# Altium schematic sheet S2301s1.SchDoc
size A3; SheetNumber: 1; SheetTotal: 1
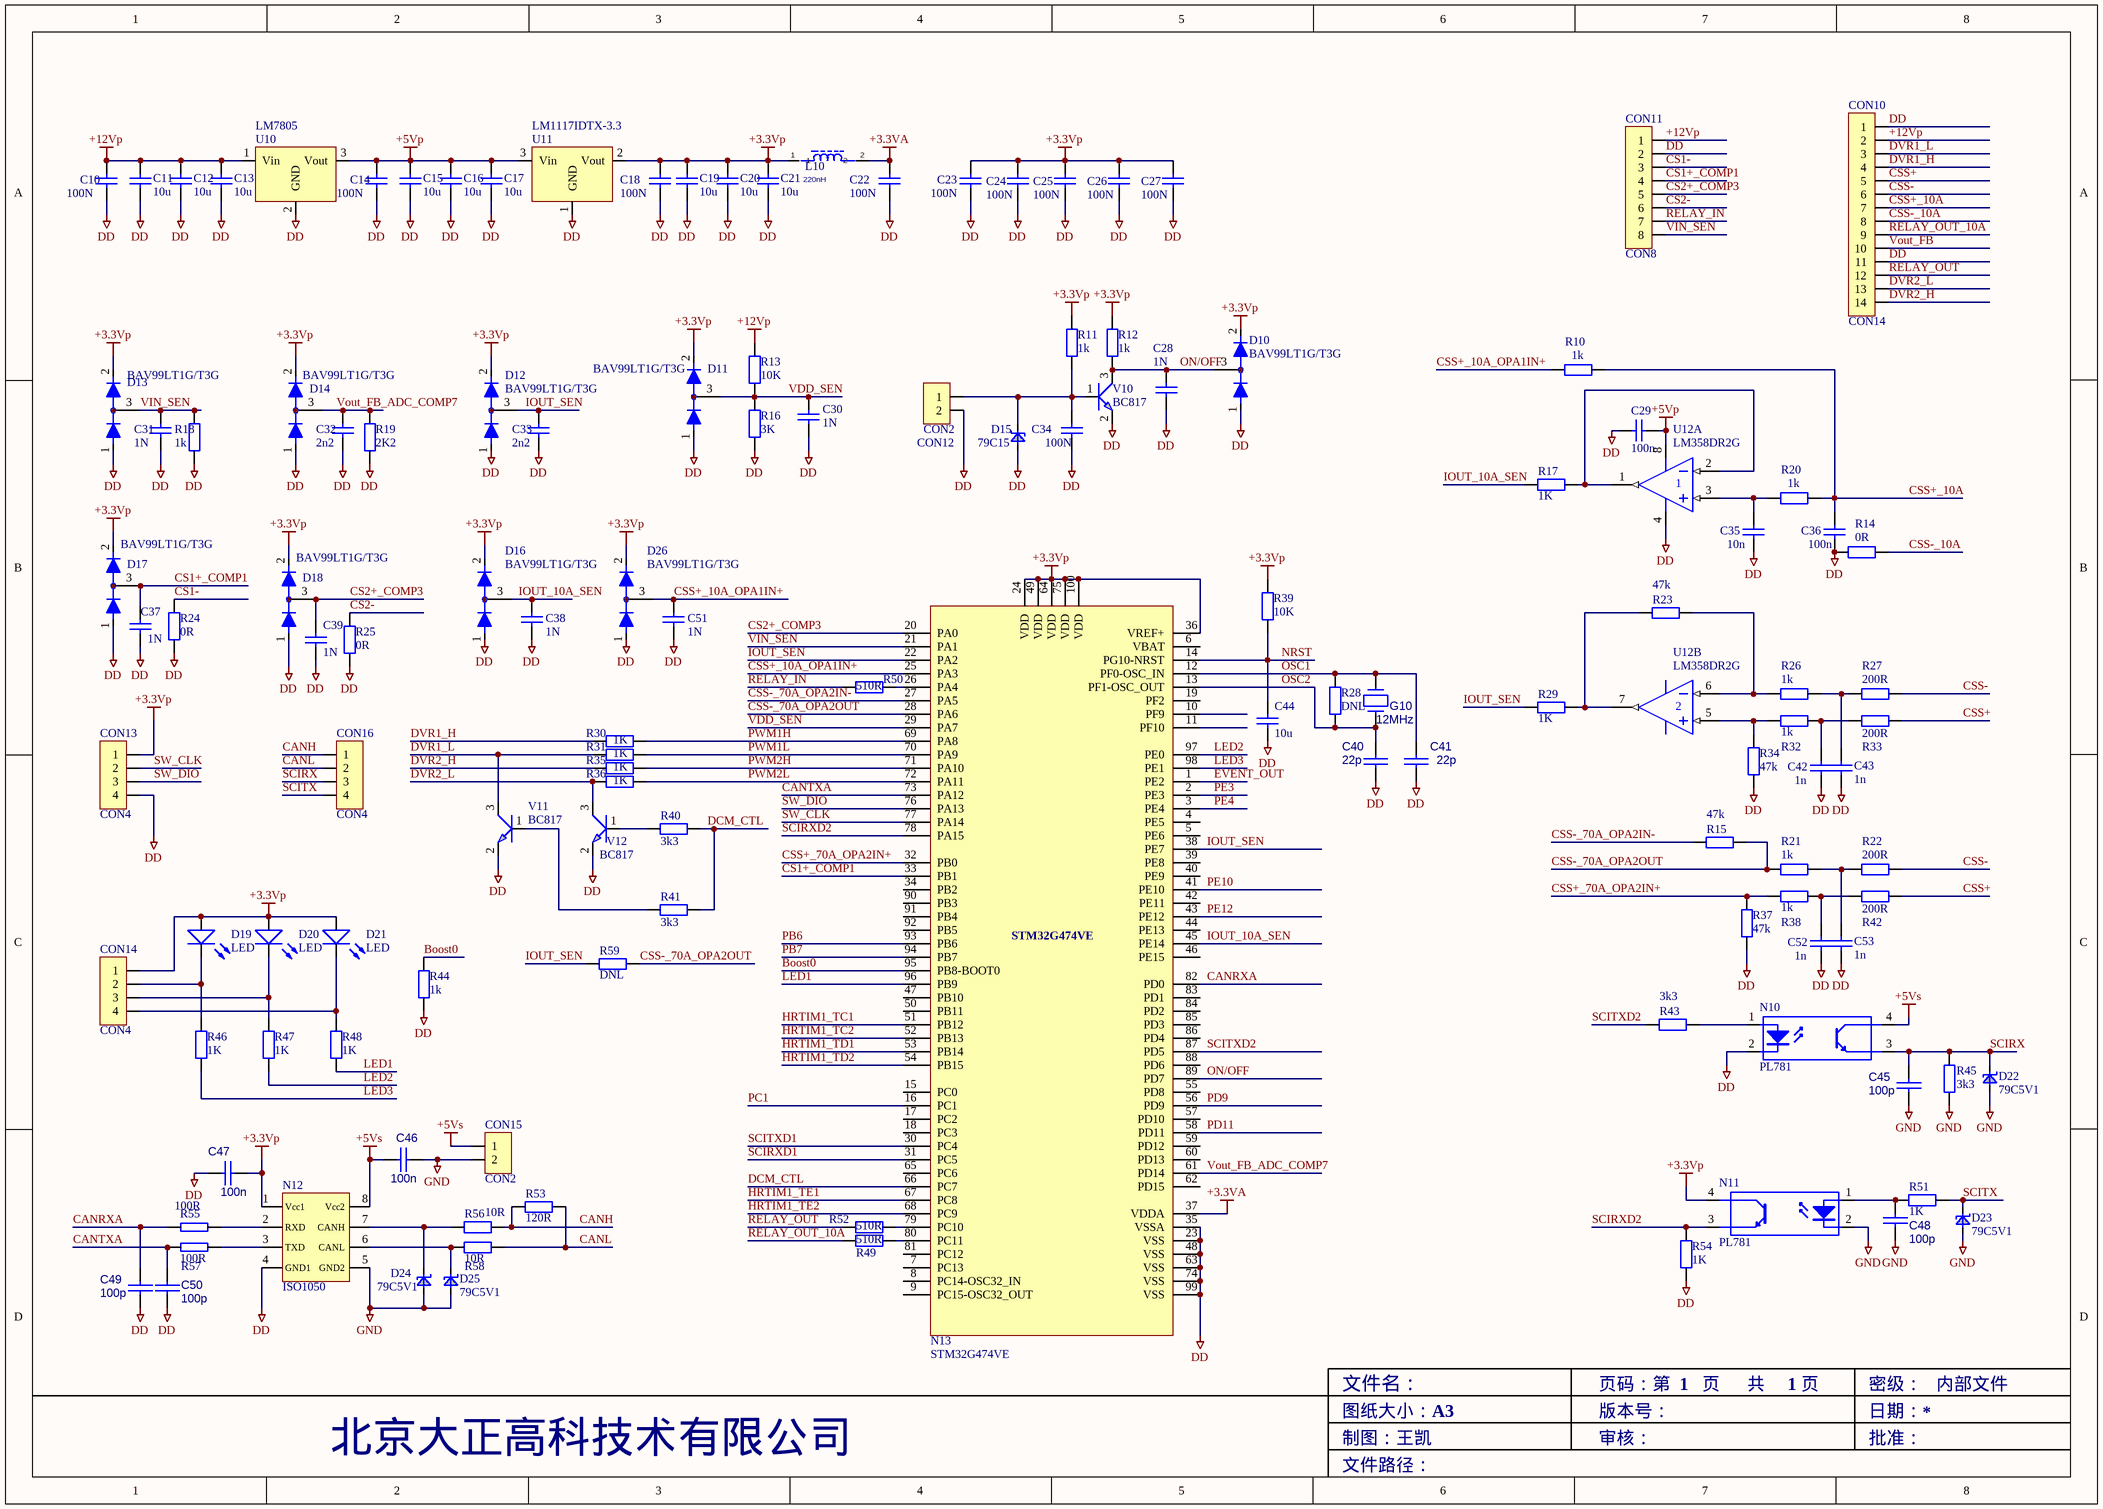
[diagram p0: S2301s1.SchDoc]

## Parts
C10  100N  [0805C]
C11  10u  [1210C]
C12  10u  [1210C]
C13  10u  [1210C]
C14  100N  [0805C]
C15  10u  [1210C]
C16  10u  [1210C]
C17  10u  [1210C]
C18  100N  [0805C]
C19  10u  [1210C]
C20  10u  [1210C]
C21  10u  [1210C]
C22  100N  [0805C]
C23  100N  [0805C]
C24  100N  [0805C]
C25  100N  [0805C]
C26  100N  [0805C]
C27  100N  [0805C]
C28  1N  [0805C]
C29  100n  [0805C]
C30  1N  [0805C]
C31  1N  [0805C]
C32  2n2  [0805C]
C33  2n2  [0805C]
C34  100N  [0805C]
C35  10n  [0805C]
C36  100n  [0805C]
C37  1N  [0805C]
C38  1N  [0805C]
C39  1N  [0805C]
C40  22p  [0805C]
C41  22p  [0805C]
C42  1n  [0805C]
C43  1n  [0805C]
C44  10u  [0805C]
C45  100p  [0805C]
C46  100n  [0805C]
C47  100n  [0805C]
C48  100p  [0805C]
C49  100p  [0805C]
C50  100p  [0805C]
C51  1N  [0805C]
C52  1n  [0805C]
C53  1n  [0805C]
CON10  CON14  [201S2X7]
CON11  CON8  [201S2X4]
CON12  CON2  [HEAD2X1]
CON13  CON4  [402+403-04]
CON14  CON4  [402+403-04]
CON15  CON2  [HEAD2X1]
CON16  CON4  [SIP4]
D10  BAV99LT1G/T3G  [SOT-23]
D11  BAV99LT1G/T3G  [SOT-23]
D12  BAV99LT1G/T3G  [SOT-23]
D13  BAV99LT1G/T3G  [SOT-23]
D14  BAV99LT1G/T3G  [SOT-23]
D15  79C15  [DO-214AC]
D16  BAV99LT1G/T3G  [SOT-23]
D17  BAV99LT1G/T3G  [SOT-23]
D18  BAV99LT1G/T3G  [SOT-23]
D19  LED  [0805_LED]
D20  LED  [0805_LED]
D21  LED  [0805_LED]
D22  79C5V1  [DO-214AC]
D23  79C5V1  [DO-214AC]
D24  79C5V1  [DO-214AC]
D25  79C5V1  [DO-214AC]
D26  BAV99LT1G/T3G  [SOT-23]
G10  12MHz  [XTAL-12MHz]
L10  220nH  [1206R]
N10  PL781  [SOP-4OPTO]
N11  PL781  [SOP-4OPTO]
N12  ISO1050  [6N136]
N13  STM32G474VE  [TQFP-100]
R10  1k  [0805R]
R11  1k  [0805R]
R12  1k  [0805R]
R13  10K  [0805R]
R14  0R  [0805R]
R15  47k  [0805R]
R16  3K  [0805R]
R17  1K  [0805R]
R18  1k  [0805R]
R19  2K2  [0805R]
R20  1k  [0805R]
R21  1k  [0805R]
R22  200R  [0805R]
R23  47k  [0805R]
R24  0R  [0805R]
R25  0R  [0805R]
R26  1k  [0805R]
R27  200R  [0805R]
R28  DNL  [0805R]
R29  1K  [0805R]
R30  1K  [0805R]
R31  1K  [0805R]
R32  1k  [0805R]
R33  200R  [0805R]
R34  47k  [0805R]
R35  1K  [0805R]
R36  1K  [0805R]
R37  47k  [0805R]
R38  1k  [0805R]
R39  10K  [0805R]
R40  3k3  [0805R]
R41  3k3  [0805R]
R42  200R  [0805R]
R43  3k3  [0805R]
R44  1k  [0805R]
R45  3k3  [0805R]
R46  1K  [0805R]
R47  1K  [0805R]
R48  1K  [0805R]
R49  510R  [0805R]
R50  510R  [0805R]
R51  1K  [0805R]
R52  510R  [0805R]
R53  120R  [0805R]
R54  1K  [0805R]
R55  100R  [0805R]
R56  10R  [0805R]
R57  100R  [0805R]
R58  10R  [0805R]
R59  DNL  [0805R]
U10  LM7805  [TO-220-1]
U11  LM1117IDTX-3.3  [TO-252]
U12  LM358DR2G  [SOIC-8]  (parts A,B of 2)
V10  BC817  [SOT-23]
V11  BC817  [SOT-23]
V12  BC817  [SOT-23]

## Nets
+3.3VA: C22.2 L10.2 N13.37(VDDA)
+3.3Vp: C18.2 C19.2 C20.2 C21.2 C23.2 C24.2 C25.2 C26.2 C27.2 C47.1 CON13.1 CON14.1 D10.2 D11.2 D12.2 D13.2 D14.2 D16.2 D17.2 D18.2 D19.A D20.A D21.A D26.2 L10.1 N11.4 N12.1(Vcc1) N13.24(VDD) N13.36(VREF+) N13.49(VDD) N13.64(VDD) N13.75(VDD) N13.100(VDD) R11.1 R12.2 R39.1 U11.2(Vout)
+5Vp: C14.2 C15.2 C16.2 C17.2 C29.1 U10.3(Vout) U11.3(Vin) U12.8(V+)
+5Vs: C46.2 CON15.1 N10.4 N12.8(Vcc2)
+12Vp: C10.2 C11.2 C12.2 C13.2 CON10.2 CON11.1 R13.2 U10.1(Vin)
DD: C10.1 C11.1 C12.1 C13.1 C14.1 C15.1 C16.1 C17.1 C18.1 C19.1 C20.1 C21.1 C22.1 C23.1 C24.1 C25.1 C26.1 C27.1 C28.1 C29.2 C30.1 C31.1 C32.1 C33.1 C34.1 C35.2 C36.2 C37.1 C38.1 C39.1 C40.2 C41.2 C42.2 C43.2 C44.1 C47.2 C49.1 C50.1 C51.1 C52.2 C53.2 CON10.1 CON10.11 CON11.2 CON12.2 CON13.4 D10.1 D11.1 D12.1 D13.1 D14.1 D15.A D16.1 D17.1 D18.1 D26.1 N10.2 N12.4(GND1) N13.23(VSS) N13.35(VSSA) N13.48(VSS) N13.63(VSS) N13.74(VSS) N13.99(VSS) R14.1 R16.1 R18.1 R19.1 R24.1 R25.1 R34.1 R37.1 R44.1 R54.2 U10.2(GND) U11.1(GND) U12.4(V-) V10.2(C) V11.2(C) V12.2(C)
GND: C45.1 C46.1 C48.1 CON15.2 D22.A D23.A D24.A D25.A N11.2 N12.5(GND2) R45.1
Boost0: N13.95(PB8-BOOT0) R44.2
CANH: CON16.1 R53.1 R56.1
CANL: CON16.2 R53.2 R58.1
CANRXA: C49.2 N13.82(PD0) R55.1
CANTXA: C50.2 N13.73(PA12) R57.1
CS1+_COMP1: C37.2 CON11.4 D17.3 N13.33(PB1)
CS1-: CON11.3 R24.2
CS2+_COMP3: C39.2 CON11.5 D18.3 N13.20(PA0)
CS2-: CON11.6 R25.2
CSS+: CON10.5 R33.2 R42.2
CSS+_10A: C36.1 CON10.7 R10.2 R20.2
CSS+_10A_OPA1IN+: C51.2 D26.3 N13.25(PA3) R10.1
CSS+_70A_OPA2IN+: N13.32(PB0) R37.2 R38.1
CSS-: CON10.6 R22.2 R27.2
CSS-_10A: CON10.8 R14.2
CSS-_70A_OPA2IN-: N13.27(PA5) R15.1
CSS-_70A_OPA2OUT: N13.28(PA6) R15.2 R21.1 R59.1
DCM_CTL: N13.66(PC7) R40.2 R41.2
DVR1_H: CON10.4 R30.1
DVR1_L: CON10.3 R31.1 V11.3(E)
DVR2_H: CON10.14 R35.1
DVR2_L: CON10.13 R36.1 V12.3(E)
EVENT_OUT: N13.1(PE2)
HRTIM1_TC1: N13.51(PB12)
HRTIM1_TC2: N13.52(PB13)
HRTIM1_TD1: N13.53(PB14)
HRTIM1_TD2: N13.54(PB15)
HRTIM1_TE1: N13.67(PC8)
HRTIM1_TE2: N13.68(PC9)
IOUT_10A_SEN: C38.2 D16.3 N13.45(PE14) R17.1
IOUT_SEN: C33.2 D12.3 N13.22(PA2) N13.38(PE7) R29.1 R59.2
LED1: N13.96(PB9) R48.1
LED2: N13.97(PE0) R47.2
LED3: N13.98(PE1) R46.2
NRST: C44.2 N13.14(PG10-NRST) R39.2
ON/OFF: C28.2 D10.3 N13.89(PD7) R12.1 V10.3(E)
OSC1: C41.1 G10.2 N13.12(PF0-OSC_IN) R28.2
OSC2: C40.1 G10.1 N13.13(PF1-OSC_OUT) R28.1
PB6: N13.93(PB6)
PB7: N13.94(PB7)
PC1: N13.16(PC1)
PD9: N13.56(PD9)
PD11: N13.58(PD11)
PE3: N13.2(PE3)
PE4: N13.3(PE4)
PE10: N13.41(PE10)
PE12: N13.43(PE12)
PWM1H: N13.69(PA8) R30.2
PWM1L: N13.70(PA9) R31.2
PWM2H: N13.71(PA10) R35.2
PWM2L: N13.72(PA11) R36.2
RELAY_IN: CON11.7 R50.1
RELAY_OUT: CON10.12 R52.1
RELAY_OUT_10A: CON10.9 R49.2
SCIRX: C45.2 CON16.3 D22.K N10.3 R45.2
SCIRXD1: N13.31(PC5)
SCIRXD2: N11.3 N13.78(PA15) R54.1
SCITX: CON16.4 D23.K R51.1
SCITXD1: N13.30(PC4)
SCITXD2: N13.87(PD5) R43.2
SW_CLK: CON13.2 N13.77(PA14)
SW_DIO: CON13.3 N13.76(PA13)
VDD_SEN: C30.2 D11.3 N13.29(PA7) R13.1 R16.2
VIN_SEN: C31.2 CON11.8 D13.3 N13.21(PA1) R18.2
Vout_FB: CON10.10
Vout_FB_ADC_COMP7: C32.2 D14.3 N13.61(PD14) R19.2
NetC34_2: C34.2 CON12.1 D15.K R11.2 V10.1(B)
NetC35_1: C35.1 R20.1 U12.3(IN+)
NetC42_1: C42.1 R32.2 R33.1
NetC43_1: C43.1 R26.2 R27.1
NetC48_2: C48.2 N11.1 R51.2
NetC52_1: C52.1 R38.2 R42.1
NetC53_1: C53.1 R21.2 R22.1
NetCON14_2: CON14.2 D19.K R46.1
NetCON14_3: CON14.3 D20.K R47.1
NetCON14_4: CON14.4 D21.K R48.2
NetD24_K: D24.K N12.7(CANH) R56.2
NetD25_K: D25.K N12.6(CANL) R58.2
NetN10_1: N10.1 R43.1
NetN12_2: N12.2(RXD) R55.2
NetN12_3: N12.3(TXD) R57.2
NetN13_26: N13.26(PA4) R50.2
NetN13_79: N13.79(PC10) R52.2
NetN13_80: N13.80(PC11) R49.1
NetR17_2: R17.2 U12.1(OUT) U12.2(IN-)
NetR23_1: R23.1 R29.2 U12.7(OUT)
NetR23_2: R23.2 R26.1 U12.6(IN-)
NetR32_1: R32.1 R34.2 U12.5(IN+)
NetR40_1: R40.1 V12.1(B)
NetR41_1: R41.1 V11.1(B)

Not connected (* = marked no-connect by the designer): N13 4(PE5) 5(PE6) 6(VBAT) 7(PC13) 8(PC14-OSC32_IN) 9(PC15-OSC32_OUT) 10(PF9) 11(PF10) 15(PC0) 17(PC2) 18(PC3) 19(PF2) 34(PB2) 39(PE8) 40(PE9) 42(PE11) 44(PE13) 46(PE15) 47(PB10) 50(PB11) 55(PD8) 57(PD10) 59(PD12) 60(PD13) 62(PD15) 65(PC6) 81(PC12) 83(PD1) 84(PD2) 85(PD3) 86(PD4) 88(PD6) 90(PB3) 91(PB4) 92(PB5)

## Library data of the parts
C10 C14 C18 C22-C39 C42-C44 C51-C53 = 0805C: 贴片电容
C11-C13 C15-C17 C19-C21 = 1206C: 贴片电容
C40 C41 = S1089_A1.S01_22p_66
C45 C46 C48-C50 = S1089_A1.S01_10n_18
C47 = S1089_A1.S01_100n_6
D10-D14 D16-D18 D26 = DIODE-D: 小信号双二极管; Text Field1: 1N4148; Text Field2: DIODE; Text Field3: PHILIPS; Text Field4: FARNELL; Text Field5: 1N4148-NSC; Text Field6: NATIONAL SEMICONDUCTOR
D15 D22-D25 = Diode-ZENER: 稳压二极管
D19-D21 = 0805 LED灯: 发光二极管
G10 = S1089_A1.S01_12MHz_65
L10 = L/2P: PCB DECAL: L009
R10-R54 R56 R58 R59 = 0805R: 贴片电阻
R55 R57 = R
U12 = LM358DR2G_[C7950]: 通用运放
V10-V12 = BC817: Medium Power NPN Transistor; Text Field1: ZTX650; Text Field3: Zetex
